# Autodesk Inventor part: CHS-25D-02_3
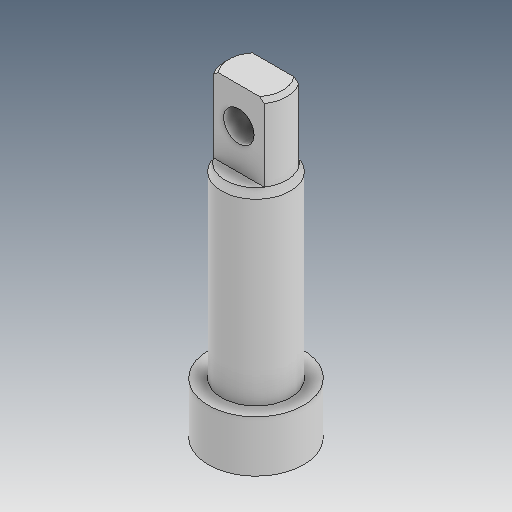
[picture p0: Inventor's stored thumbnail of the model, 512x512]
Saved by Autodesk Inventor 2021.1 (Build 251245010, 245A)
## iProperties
Created: 2019-05
Part Number: CHS-25D-02_3
Material: Ogólny
Document SubType Name: Modeling
Designer: user
Density: 1 g/cm^3
Appearance: Domyślna
Author: user
Revision Number: ÈÎºÎ
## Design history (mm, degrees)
feature "ÊäÈë1"
feature "ÊäÈë2"
node "Bryła1"
node "Bryła2"
